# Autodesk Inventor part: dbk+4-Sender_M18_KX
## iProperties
Shininess: 20.0
Length Units: 11269
Angle Units: 11279
Time Units: 11290
Mass Units: 11283
Length Display Precision: 2
Angle Display Precision: 2
Part Number: dbk+4-Sender_M18_KX
Material: Nichtrostender Stahl - 440C
Document SubType Name: Modellieren
Description: dbk-4/Sender/M18/K2
Checked By: Alves
Created: 2005-08
Designer: Ohle
Manufacturer: Standard
Standards Organization: Custom
Density: 0.0
Volumn: 0.0
Area: 0.0
PropertySet Name: Model Information
Control State: 0
Master: False
Checked Out: False
BESTELLNUMMER: dbk-4/Sender/M18/K1
ME: ST
Title: dbk-4 Sensoren
Author: Ohle
Comments: keine Bemerkung
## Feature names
1. dbk-4 Sender [Revolution]
2. Extrusion6
3. Extrusion7
